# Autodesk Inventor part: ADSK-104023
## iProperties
Shininess: 0.0
Created: 2000-09
Part Number: ADSK-104023
Document SubType Name: Modeling
Stock Number: ADSK-104023
Density: 1 g/cm^3
Density: 0.0
Volumn: 0.0
Area: 0.0
PropertySet Name: Model Information
Control State: 0
Master: False
Checked Out: False
Author: gao
